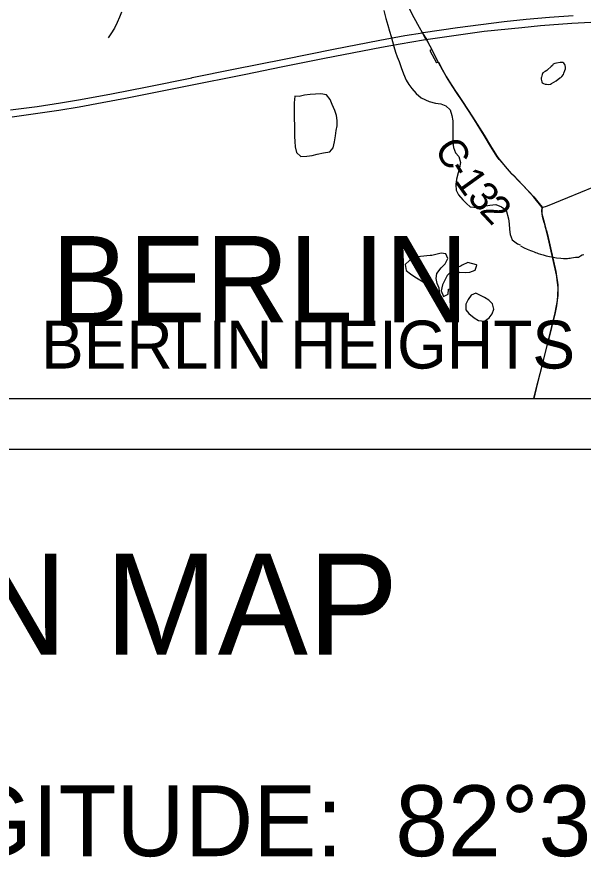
# Model space of a CAD drawing. Extents: x 0 to 34, y 0 to 22.
# Drawn here: x 5.694 to 6.813, y 13.194 to 14.854 of the extents above; entities that cross this region are included whole.
import ezdxf

# ---------------------------------------------------------------- set-up
doc = ezdxf.new("R2010")
doc.units = 0
for name, color, linetype in [('GM_X_Corporation', 7, 'Continuous'), ('GM_X_Corporation_Text', 7, 'Continuous'), ('GM_X_County_Road', 7, 'Continuous'), ('GM_X_County_Road_Text', 7, 'Continuous'), ('GM_X_Interstate_Route', 7, 'Continuous'), ('GM_X_Minor_Lake', 7, 'Continuous'), ('GM_X_Minor_River', 7, 'Continuous'), ('GM_X_Township_Road', 7, 'Continuous'), ('GM_X_Township_Text', 7, 'Continuous'), ('SH_Data', 7, 'Continuous'), ('SH_Text', 7, 'Continuous')]:
    doc.layers.add(name, color=color, linetype=linetype)

msp = doc.modelspace()

# ---------------------------------------------------------------- linework, layer by layer
at = {"layer": 'GM_X_Corporation'}
for points in [[(2.1, 20.7089), (2.1, 14.1), (8.9, 14.1), (8.9, 18.9067)], [(4.4234, 14.8562), (4.4253, 14.7443), (4.427, 14.6635), (4.4269, 14.6591), (4.4274, 14.64), (4.4276, 14.6307), (4.4279, 14.6184), (4.4282, 14.6082), (4.4282, 14.5944), (4.4285, 14.5905), (4.4301, 14.5114), (4.431, 14.4741), (4.4318, 14.4347), (4.4315, 14.4227), (4.4317, 14.396), (4.4325, 14.3733), (4.4327, 14.3684), (4.4332, 14.3373), (4.4348, 14.2876), (4.437, 14.154), (4.4374, 14.1), (8.9, 14.1), (8.9, 16.8293)], [(6.4704, 14.8695), (6.4789, 14.8529), (6.4895, 14.834), (6.4954, 14.8236), (6.5002, 14.8149), (6.5037, 14.8103), (6.5066, 14.8041), (6.5142, 14.7898), (6.5102, 14.7877), (6.5237, 14.7637), (6.5244, 14.7639), (6.5273, 14.765), (6.5354, 14.7498), (6.5429, 14.7362), (6.5494, 14.7256), (6.5613, 14.7076), (6.563, 14.7051), (6.575, 14.6871), (6.5948, 14.6566), (6.6174, 14.6205), (6.6301, 14.5992), (6.6434, 14.5782), (6.6471, 14.5732), (6.6593, 14.5588), (6.6718, 14.5451), (6.6767, 14.5402), (6.6842, 14.5323), (6.6944, 14.5215), (6.7156, 14.4985), (6.7264, 14.4853), (6.7323, 14.4781), (6.7315, 14.4718), (6.7319, 14.4655), (6.7327, 14.4605), (6.7346, 14.4534), (6.7361, 14.4484), (6.7371, 14.445), (6.7388, 14.4383), (6.7398, 14.4346), (6.7407, 14.4314), (6.7428, 14.4243), (6.7593, 14.3509), (6.7608, 14.3417), (6.7618, 14.334), (6.7624, 14.33), (6.7631, 14.3245), (6.7635, 14.3197), (6.7633, 14.304), (6.7622, 14.2946), (6.7603, 14.2835), (6.7578, 14.2702), (6.7439, 14.2135), (6.7416, 14.2045), (6.7318, 14.1651), (6.7203, 14.1198), (6.7156, 14.1), (7.647, 14.1)]]:
    msp.add_lwpolyline(points, dxfattribs=at)
at = {"layer": 'GM_X_County_Road'}
for points in [[(6.5146, 14.789), (6.5068, 14.8036), (6.5039, 14.8097), (6.5004, 14.8144), (6.4956, 14.823), (6.4897, 14.8334), (6.4791, 14.8523), (6.4706, 14.8689), (6.4573, 14.8971), (6.425, 14.968)], [(6.5277, 14.7643), (6.5197, 14.7794), (6.5146, 14.789)], [(6.7325, 14.4775), (6.7158, 14.4979), (6.6946, 14.5209), (6.6844, 14.5317), (6.677, 14.5396), (6.672, 14.5445), (6.6595, 14.5583), (6.6473, 14.5727), (6.6436, 14.5777), (6.6303, 14.5986), (6.6176, 14.62), (6.595, 14.656), (6.5752, 14.6866), (6.5616, 14.707), (6.5496, 14.7251), (6.5431, 14.7357), (6.5356, 14.7493), (6.5277, 14.7643)]]:
    msp.add_lwpolyline(points, dxfattribs=at)
at = {"layer": 'GM_X_Interstate_Route'}
msp.add_line((6.5575, 14.8176), (6.5624, 14.8184), dxfattribs=at)
for points in [[(5.6817, 14.6703), (5.7341, 14.6774), (5.7802, 14.6844), (5.8201, 14.691), (5.8812, 14.7021), (5.9514, 14.7157), (6.0398, 14.7341), (6.0407, 14.7343), (6.1221, 14.7506), (6.2227, 14.771), (6.3202, 14.7905), (6.4117, 14.8084), (6.4606, 14.8173), (6.4956, 14.823), (6.4965, 14.8232), (6.4973, 14.8233), (6.5649, 14.8333), (6.6111, 14.8395), (6.6574, 14.845), (6.7006, 14.8496), (6.747, 14.8536), (6.7935, 14.8571)], [(6.5624, 14.8184), (6.5714, 14.8197), (6.6176, 14.826), (6.6919, 14.8335), (6.7291, 14.8369), (6.791, 14.8417), (6.8283, 14.844), (6.8842, 14.8465), (6.937, 14.8484), (6.9836, 14.8492), (7.0155, 14.8493)], [(6.5021, 14.8095), (6.5039, 14.8097), (6.5069, 14.8102), (6.5575, 14.8176)], [(5.6851, 14.657), (5.7312, 14.6632), (5.7773, 14.6701), (5.8172, 14.6766), (5.863, 14.6849), (5.9088, 14.6937), (6.0277, 14.7172), (6.1465, 14.7413), (6.2166, 14.7554), (6.3019, 14.7726), (6.4148, 14.7947), (6.4515, 14.8013), (6.4976, 14.8088), (6.5021, 14.8095)]]:
    msp.add_lwpolyline(points, dxfattribs=at)
at = {"layer": 'GM_X_Minor_Lake'}
for points in [[(6.7675, 14.7335), (6.769, 14.7347), (6.7709, 14.7362), (6.7743, 14.7404), (6.7754, 14.7431), (6.7772, 14.7481), (6.7783, 14.7519), (6.7787, 14.7546), (6.7779, 14.758), (6.7771, 14.7599), (6.7752, 14.7629), (6.7733, 14.7644), (6.7702, 14.7644), (6.7676, 14.7639), (6.7607, 14.7627), (6.7573, 14.7619), (6.7539, 14.7608), (6.7524, 14.7581), (6.7498, 14.7562), (6.7494, 14.7558)], [(6.7494, 14.7558), (6.7434, 14.75), (6.7415, 14.7481), (6.7381, 14.7465), (6.7339, 14.7434), (6.7324, 14.7404), (6.731, 14.7354), (6.7306, 14.7335), (6.7303, 14.7312), (6.7307, 14.7282), (6.7314, 14.7259), (6.7326, 14.724), (6.7349, 14.7225), (6.7383, 14.7214), (6.7406, 14.721), (6.7456, 14.7207), (6.7486, 14.7215), (6.7509, 14.7223), (6.7599, 14.7281), (6.7675, 14.7335)], [(6.2433, 14.6978), (6.2423, 14.6841), (6.242, 14.6735), (6.242, 14.6632), (6.2421, 14.6626)], [(6.2421, 14.6626), (6.2427, 14.6301), (6.2431, 14.618), (6.2432, 14.6081), (6.2444, 14.5975), (6.2468, 14.5861), (6.2552, 14.5785), (6.2673, 14.579), (6.2776, 14.5806), (6.2878, 14.5829), (6.3, 14.5856), (6.3125, 14.5876), (6.3193, 14.5957), (6.3218, 14.6075), (6.3237, 14.6193), (6.3251, 14.6295), (6.3269, 14.639), (6.3272, 14.6497), (6.3257, 14.6592), (6.3225, 14.6694), (6.3171, 14.6812), (6.3133, 14.691), (6.306, 14.7005), (6.2946, 14.7019), (6.2737, 14.7011), (6.2627, 14.6995), (6.2521, 14.6967), (6.2433, 14.6978)], [(6.5107, 14.3826), (6.492, 14.381), (6.4806, 14.379), (6.4704, 14.3732), (6.4617, 14.3648), (6.4633, 14.353), (6.4721, 14.3463), (6.4809, 14.3406), (6.4908, 14.3346), (6.4992, 14.3297), (6.508, 14.3233), (6.5153, 14.3157), (6.5206, 14.307), (6.5302, 14.3067), (6.5289, 14.3181), (6.5251, 14.3276), (6.5227, 14.3371), (6.5242, 14.3473), (6.5328, 14.3584), (6.5408, 14.3665), (6.546, 14.3768), (6.5418, 14.3862), (6.5326, 14.3873)], [(6.5326, 14.3873), (6.5144, 14.383), (6.5107, 14.3826)], [(6.5722, 14.3625), (6.5652, 14.3589), (6.5549, 14.3539), (6.5444, 14.3431), (6.5399, 14.334), (6.5354, 14.3248), (6.5324, 14.3127), (6.5374, 14.3017), (6.5462, 14.3063), (6.5472, 14.3165), (6.559, 14.317), (6.5662, 14.3247), (6.5653, 14.3364), (6.5603, 14.3459), (6.5694, 14.3501), (6.58, 14.3494), (6.5895, 14.3499), (6.6002, 14.3538), (6.6031, 14.3637), (6.6027, 14.364)], [(6.6027, 14.364), (6.5856, 14.3689), (6.5743, 14.3635), (6.5722, 14.3625)], [(6.6012, 14.3085), (6.5918, 14.3047), (6.5861, 14.2959), (6.5812, 14.2864), (6.5813, 14.2757), (6.5876, 14.268)], [(6.5876, 14.268), (6.5978, 14.2598), (6.6065, 14.2542), (6.6183, 14.2531), (6.6274, 14.2593), (6.6338, 14.2673), (6.6368, 14.2768), (6.634, 14.2874), (6.6272, 14.2942), (6.618, 14.2999), (6.6012, 14.3085)]]:
    msp.add_lwpolyline(points, dxfattribs=at)
at = {"layer": 'GM_X_Minor_River'}
for points in [[(5.9007, 14.8637), (5.8973, 14.8538), (5.8924, 14.8431), (5.8872, 14.8321), (5.8801, 14.8206), (5.8748, 14.8126)], [(6.4196, 14.8666), (6.4235, 14.851), (6.4274, 14.8381), (6.4309, 14.826), (6.4336, 14.8157), (6.4363, 14.8059), (6.4394, 14.7956), (6.4426, 14.7846), (6.446, 14.7751), (6.4495, 14.766), (6.4538, 14.7543), (6.4584, 14.7418), (6.4638, 14.7292), (6.4688, 14.7205), (6.4746, 14.7126), (6.4834, 14.7028), (6.4929, 14.6945), (6.5093, 14.6873), (6.5215, 14.6836), (6.5318, 14.6825), (6.5421, 14.6788), (6.5505, 14.6705), (6.554, 14.6591), (6.5556, 14.6489), (6.556, 14.6378), (6.5557, 14.6272), (6.5558, 14.6154), (6.5559, 14.6059), (6.5571, 14.5964), (6.5609, 14.5858), (6.5678, 14.5782), (6.571, 14.5668), (6.5687, 14.5558), (6.5662, 14.5459), (6.5632, 14.5333), (6.5614, 14.5227), (6.5622, 14.512), (6.5672, 14.5029), (6.5753, 14.4927)], [(6.5753, 14.4927), (6.5825, 14.4852), (6.5902, 14.4791), (6.6039, 14.4773), (6.6171, 14.4801), (6.6289, 14.4824), (6.6407, 14.4833), (6.6517, 14.4788), (6.6609, 14.472), (6.6659, 14.4549), (6.6668, 14.445), (6.668, 14.4344), (6.6692, 14.4245), (6.6731, 14.4135), (6.6834, 14.406), (6.6891, 14.4037)], [(6.6894, 14.4021), (6.6967, 14.3979), (6.7025, 14.395), (6.7093, 14.3924), (6.7131, 14.3913), (6.7162, 14.3898), (6.7189, 14.389), (6.7215, 14.3879), (6.7246, 14.3868), (6.7288, 14.3853), (6.7341, 14.3839), (6.7402, 14.3824), (6.7471, 14.381), (6.7539, 14.3795), (6.7604, 14.3781), (6.7692, 14.3774), (6.7745, 14.3771), (6.7787, 14.3771), (6.7821, 14.3771), (6.7847, 14.3776), (6.7874, 14.3776), (6.7904, 14.3784), (6.7942, 14.3788), (6.7984, 14.3792), (6.8022, 14.3793), (6.8041, 14.3797), (6.8083, 14.3824), (6.8113, 14.3839), (6.8143, 14.3847)]]:
    msp.add_lwpolyline(points, dxfattribs=at)
at = {"layer": 'GM_X_Township_Road'}
for points in [[(6.7325, 14.4775), (6.7428, 14.4806), (6.783, 14.4971), (6.8344, 14.5185), (6.8986, 14.5448)], [(6.7159, 14.1), (6.7205, 14.1193), (6.732, 14.1646), (6.7441, 14.2129), (6.7581, 14.2696), (6.7606, 14.283), (6.7624, 14.2941), (6.7635, 14.3035), (6.7637, 14.3192), (6.7633, 14.324), (6.7627, 14.3294), (6.762, 14.3334), (6.761, 14.3411), (6.7595, 14.3503), (6.743, 14.4238), (6.7409, 14.4309), (6.7401, 14.434), (6.739, 14.4378), (6.7373, 14.4445), (6.7363, 14.4478), (6.7348, 14.4528), (6.7329, 14.46), (6.7321, 14.465), (6.7317, 14.4713), (6.7325, 14.4775)]]:
    msp.add_lwpolyline(points, dxfattribs=at)
at = {"layer": 'SH_Data'}
for p, q in [((2.1, 14.1), (8.9, 14.1)), ((2, 14), (9, 14))]:
    msp.add_line(p, q, dxfattribs=at)

# ---------------------------------------------------------------- texts
at = {"layer": 'GM_X_Corporation_Text'}
msp.add_text('BERLIN HEIGHTS', height=0.094697, rotation=0, dxfattribs=at).set_placement((5.7418, 14.1594))
at = {"layer": 'GM_X_County_Road_Text'}
for s, rotation, p in [('C', 301.5582, (6.5179, 14.5938)), ('-', 302.0968, (6.5427, 14.5535)), ('1', 305.6465, (6.5572, 14.5306)), ('3', 312.4983, (6.5823, 14.4964)), ('2', 313.0894, (6.6064, 14.4701))]:
    msp.add_text(s, height=0.0568, rotation=rotation, dxfattribs=at).set_placement(p)
at = {"layer": 'GM_X_Township_Text'}
msp.add_text('BERLIN', height=0.17045, rotation=0, dxfattribs=at).set_placement((5.7629, 14.2509))
at = {"layer": 'SH_Text'}
for s, height, p in [('LOCATION MAP', 0.2, (4.4269, 13.5938)), ('LATITUDE:  41°22\'01"     LONGITUDE:  82°30\'43"', 0.14, (3.071, 13.1959))]:
    msp.add_text(s, height=height, dxfattribs=at).set_placement(p)

doc.saveas('drawing.dxf')
